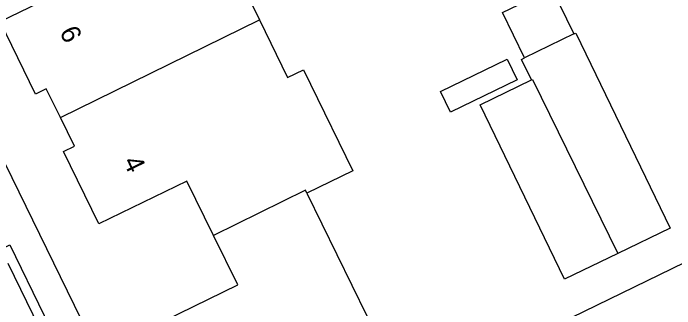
# Model space of a CAD drawing. Extents: x 160457 to 162082, y 388340 to 389736.
# Drawn here: x 160872.78 to 160907, y 388912.08 to 388927.38 of the extents above; entities that cross this region are included whole.
import ezdxf

# ---------------------------------------------------------------- set-up
doc = ezdxf.new("R2010")
doc.units = 0
for name, color, linetype in [('IMGEO_Pand', 7, 'Continuous'), ('IMGEO_Pand_nummerreeks', 7, 'Continuous'), ('IMGEO_Voetpad_open', 7, 'Continuous')]:
    doc.layers.add(name, color=color, linetype=linetype)

msp = doc.modelspace()

# ---------------------------------------------------------------- linework, layer by layer
at = {"layer": 'IMGEO_Pand'}
for points in [[(160882.398, 388935.501), (160883.933, 388932.36), (160883.115, 388931.96), (160885.523, 388927.033)], [(160875.226, 388921.978), (160874.494, 388923.466), (160873.928, 388923.19), (160872.1, 388926.948), (160876.717, 388929.199), (160875.346, 388932.003)], [(160899.236, 388925.064), (160898.086, 388927.425), (160900.641, 388928.67), (160901.791, 388926.309)], [(160875.226, 388921.978), (160885.523, 388927.033)], [(160885.523, 388927.033), (160886.979, 388924.053), (160887.797, 388924.452), (160888.157, 388923.716), (160890.351, 388919.223), (160887.97, 388918.059)], [(160901.791, 388926.309), (160899.236, 388925.064)], [(160901.791, 388926.309), (160901.886, 388926.355), (160906.766, 388916.253), (160904.061, 388914.947)], [(160898.851, 388923.935), (160895.408, 388922.258), (160894.889, 388923.322), (160898.332, 388925), (160898.851, 388923.935)], [(160899.592, 388923.932), (160899.078, 388924.987), (160899.236, 388925.064)], [(160904.061, 388914.947), (160901.301, 388913.614), (160896.94, 388922.64), (160899.592, 388923.932)], [(160899.592, 388923.932), (160899.637, 388923.954), (160904.061, 388914.947)], [(160883.151, 388915.868), (160881.77, 388918.694), (160877.216, 388916.477), (160875.386, 388920.224), (160875.952, 388920.5), (160875.226, 388921.978)], [(160887.97, 388918.059), (160891.847, 388910.126), (160882.539, 388905.576), (160879.852, 388911.09), (160884.4, 388913.312), (160883.151, 388915.868)], [(160887.97, 388918.059), (160887.896, 388918.223), (160883.151, 388915.868)]]:
    msp.add_lwpolyline(points, dxfattribs=at)
at = {"layer": 'IMGEO_Voetpad_open'}
for points in [[(160836.379, 388993.364), (160850.87, 388963.642), (160880.226, 388903.473)], [(160882.906, 388902.468), (160883.834, 388902.918), (160891.286, 388906.53), (160901.022, 388911.309), (160908.826, 388915.117), (160918.922, 388920.047), (160928.435, 388924.714)], [(160872.155, 388915.173), (160872.604, 388915.391), (160876.153, 388908.07), (160875.704, 388907.852)], [(160872.512, 388914.437), (160875.414, 388908.45)]]:
    msp.add_lwpolyline(points, dxfattribs=at)

# ---------------------------------------------------------------- texts
at = {"layer": 'IMGEO_Pand_nummerreeks'}
for s, rotation, p in [('6', 295.9396, (160875.16, 388926.42)), ('4', 296.0305, (160878.445, 388919.704))]:
    msp.add_text(s, height=1, rotation=rotation, dxfattribs=at).set_placement(p)

doc.saveas('drawing.dxf')
